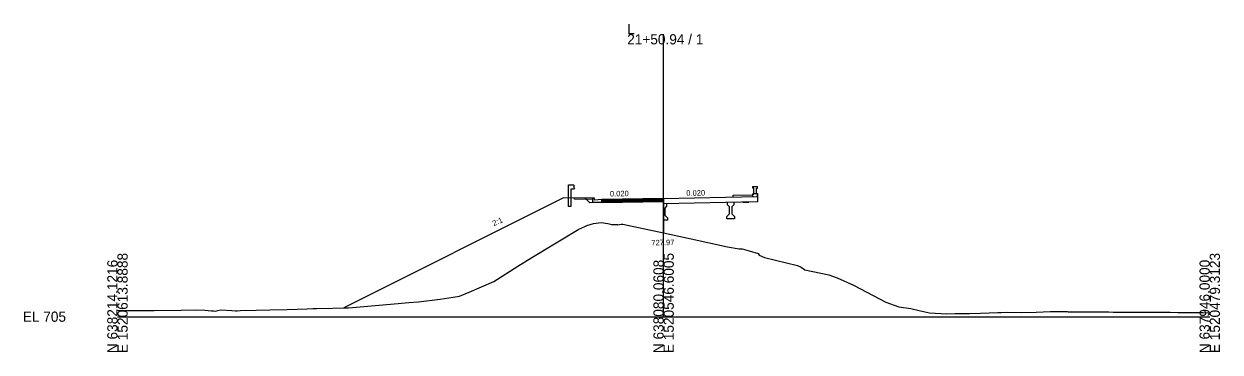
# Model space of a CAD drawing. Extents: x -26 to 3903, y -10 to 9531.
# Drawn here: x 2274.3 to 2602.8, y 490.3 to 580.3 of the extents above; entities that cross this region are included whole.
import ezdxf

# ---------------------------------------------------------------- set-up
doc = ezdxf.new("R2010")
doc.units = 0
for name, color, linetype in [('Exist Cross Section Cell', 7, 'Continuous'), ('Exist XS Center Line Elevation Label', 7, 'Continuous'), ('Exist XS Ground Line', 7, 'Continuous'), ('Old_Level_63', 7, 'Continuous'), ('Prop CMT Guardrail Graphics', 7, 'Continuous'), ('Prop CMT Pvmt Course 1', 7, 'Continuous'), ('Prop CMT Pvmt Course 2', 7, 'Continuous'), ('Prop CMT Pvmt Course 3', 7, 'Continuous'), ('Prop CMT Pvmt Surface', 7, 'Continuous'), ('Prop CMT Slope Grass', 7, 'Continuous'), ('Prop CMT Subgrade Earthwork', 7, 'Continuous'), ('Prop XS Conc Monolithic Island', 7, 'Continuous'), ('Prop XS Earthwork Shape', 7, 'Continuous'), ('Prop XS Finish Grade', 7, 'Continuous'), ('Prop XS Finish Grade Concrete', 7, 'Continuous'), ('Prop XS SE Text', 7, 'Continuous'), ('Prop XS Side Slope Text', 7, 'Continuous')]:
    doc.layers.add(name, color=color, linetype=linetype)

msp = doc.modelspace()

# ---------------------------------------------------------------- linework, layer by layer
at = {"layer": 'Exist Cross Section Cell'}
for p, q in [((2450, 500), (2450, 577.45)), ((2300, 500), (2450, 500)), ((2450, 500), (2600, 500))]:
    msp.add_line(p, q, dxfattribs=at)
at = {"layer": 'Exist XS Ground Line'}
msp.add_lwpolyline([(2300, 501.78), (2301.58, 501.71), (2310.09, 501.71), (2317.52, 501.78), (2321.61, 501.89), (2323.99, 501.76), (2325.83, 501.62), (2326.47, 501.58), (2326.93, 501.51), (2327.56, 501.69), (2328.41, 501.87), (2331.44, 501.74), (2332.45, 501.62), (2332.84, 501.63), (2333.69, 501.65), (2338.1, 501.81), (2341.83, 501.86), (2346.57, 501.94), (2352.12, 502.16), (2353.7, 502.24), (2354.74, 502.28), (2363.47, 502.47), (2364.51, 502.52), (2378.06, 503.7), (2379, 503.76), (2380.03, 503.85), (2382.69, 504.11), (2388.59, 504.76), (2392.16, 505.37), (2393.94, 505.58), (2396.56, 506.74), (2403.34, 509.61), (2409.94, 513.84), (2413.83, 516.23), (2426.69, 524.03), (2428.32, 524.75), (2428.95, 524.99), (2430.74, 525.56), (2432.85, 525.82), (2434.66, 525.54), (2435.09, 525.43), (2435.67, 525.26), (2436.69, 525.26), (2437.35, 525.29), (2437.42, 525.17), (2438.32, 525.32), (2438.84, 525.34), (2450, 522.97), (2452.06, 522.53), (2457.59, 521.33), (2467.51, 519.16), (2470.73, 518.59), (2471.58, 518.57), (2473.46, 518.09), (2475.95, 517.3), (2476.26, 516.89), (2477.72, 516.26), (2486.79, 514.03), (2487.74, 513.61), (2488.83, 512.82), (2495.37, 511.48), (2497.64, 510.68), (2502.19, 508.65), (2511.06, 503.97), (2514.6, 502.67), (2517.91, 502.26), (2520.56, 501.58), (2523.05, 501.09), (2527.79, 500.78), (2530.11, 500.84), (2534.06, 500.9), (2537.01, 500.97), (2541.79, 501.15), (2542.69, 501.18), (2544.15, 501.2), (2548.35, 501.18), (2552.3, 501.27), (2556.2, 501.38), (2558.87, 501.42), (2560.31, 501.38), (2560.81, 501.38), (2561.12, 501.37), (2562.54, 501.36), (2564.02, 501.36), (2564.69, 501.35), (2565.65, 501.35), (2566.19, 501.35), (2566.68, 501.34), (2568.21, 501.33), (2569.53, 501.31), (2569.86, 501.31), (2570.28, 501.3), (2572.33, 501.29), (2573.51, 501.28), (2575.13, 501.27), (2575.86, 501.27), (2577.92, 501.26), (2579.1, 501.25), (2580.73, 501.24), (2581.44, 501.24), (2583.51, 501.23), (2585.64, 501.22), (2586.53, 501.22), (2586.98, 501.22), (2588.41, 501.21), (2589.12, 501.2), (2591.27, 501.19), (2592.12, 501.18), (2592.54, 501.18), (2594.48, 501.19), (2594.84, 501.19), (2596.24, 501.16), (2597.6, 501.13), (2598.12, 501.12), (2599.57, 501.09), (2600, 501.09)], dxfattribs=at)
at = {"layer": 'Old_Level_63'}
for p, q in [((2431, 531.95), (2431, 532.45)), ((2433, 532.1), (2431, 531.95))]:
    msp.add_line(p, q, dxfattribs=at)
for points in [[(2425.5, 532.21), (2425.5, 532.55)], [(2430.5, 532.46), (2430.5, 532.12)], [(2430.5, 532.45), (2430.5, 531.42), (2433, 531.51)], [(2430.5, 532.11), (2425.5, 532.21)], [(2433, 531.51), (2433, 532.1)]]:
    msp.add_lwpolyline(points, dxfattribs=at)
at = {"layer": 'Prop CMT Guardrail Graphics'}
for points in [[(2423.9, 530.17), (2423.9, 536.17)], [(2423.9, 536.17), (2425.23, 536.17), (2425.5, 535.88)], [(2425.5, 535.88), (2425.23, 535.58)], [(2425.23, 535.58), (2425.5, 535.29)], [(2425.5, 535.29), (2425.23, 535), (2424.56, 535)], [(2424.56, 535), (2424.56, 530.17)], [(2424.56, 530.17), (2423.9, 530.17)]]:
    msp.add_lwpolyline(points, dxfattribs=at)
at = {"layer": 'Prop CMT Pvmt Course 1'}
msp.add_line((2450, 532.44), (2433, 532.1), dxfattribs=at)
msp.add_lwpolyline([(2433, 531.85), (2450, 532.19)], dxfattribs=at)
at = {"layer": 'Prop CMT Pvmt Course 2'}
for points in [[(2450, 532.19), (2433, 531.85)], [(2433, 531.85), (2433, 531.51)], [(2433, 531.51), (2450, 531.85)]]:
    msp.add_lwpolyline(points, dxfattribs=at)
at = {"layer": 'Prop CMT Pvmt Course 3'}
for points in [[(2450, 531.85), (2433, 531.51)], [(2433, 531.26), (2450, 531.6)]]:
    msp.add_lwpolyline(points, dxfattribs=at)
at = {"layer": 'Prop CMT Pvmt Surface'}
msp.add_line((2450, 532.44), (2433, 532.1), dxfattribs=at)
msp.add_lwpolyline([(2450, 532.44), (2433, 532.1)], dxfattribs=at)
at = {"layer": 'Prop CMT Slope Grass'}
for p, q in [((2430.5, 532.45), (2422.5, 532.61)), ((2450, 532.44), (2450, 522.98))]:
    msp.add_line(p, q, dxfattribs=at)
msp.add_lwpolyline([(2422.5, 532.61), (2362.17, 502.44)], dxfattribs=at)
at = {"layer": 'Prop CMT Subgrade Earthwork'}
for points in [[(2433, 531.26), (2429.74, 531.2), (2428.46, 532.49)], [(2450, 531.6), (2433, 531.26)]]:
    msp.add_lwpolyline(points, dxfattribs=at)
at = {"layer": 'Prop XS Conc Monolithic Island'}
for p, q in [((2474.53, 535.21), (2474.53, 535.71)), ((2474.53, 535.71), (2475.78, 535.71)), ((2475.78, 535.21), (2475.78, 535.71)), ((2474.78, 535.21), (2474.53, 535.21)), ((2474.53, 532.95), (2474.53, 533.71)), ((2474.53, 533.71), (2474.78, 533.71)), ((2474.78, 533.71), (2474.78, 535.21)), ((2475.53, 533.71), (2475.53, 535.21)), ((2475.53, 535.21), (2475.78, 535.21)), ((2475.78, 533.71), (2475.53, 533.71)), ((2475.78, 532.95), (2475.78, 533.71))]:
    msp.add_line(p, q, dxfattribs=at)
for points in [[(2450, 532.44), (2467, 532.78), (2475.78, 532.95)], [(2475.75, 532.98), (2475.78, 531.45)], [(2475.78, 531.45), (2467, 531.28), (2450, 530.94)], [(2450.83, 530.27), (2450.33, 529.77)], [(2450.33, 529.77), (2450.33, 527.85)], [(2450.83, 530.95), (2450.83, 530.27)], [(2467.59, 530.64), (2467.59, 531.29)], [(2468.09, 530.14), (2467.59, 530.64)], [(2468.09, 528.22), (2468.09, 530.14)], [(2469.26, 530.64), (2468.76, 530.14)], [(2468.76, 530.14), (2468.76, 528.22)], [(2469.26, 531.32), (2469.26, 530.64)], [(2471.75, 531.37), (2472.58, 531.39), (2473.42, 531.4)], [(2451.08, 526.44), (2450, 526.44)], [(2450.33, 527.85), (2451.08, 527.1)], [(2451.08, 527.1), (2451.08, 526.44)], [(2467.34, 527.47), (2468.09, 528.22)], [(2467.34, 526.8), (2467.34, 527.47)], [(2469.51, 526.8), (2468.42, 526.8), (2467.34, 526.8)], [(2468.76, 528.22), (2469.51, 527.47)], [(2469.51, 527.47), (2469.51, 526.8)]]:
    msp.add_lwpolyline(points, dxfattribs=at)
at = {"layer": 'Prop XS Earthwork Shape'}
for points in [[(2363.47, 502.47), (2364.51, 502.52), (2378.06, 503.7), (2379, 503.76), (2380.03, 503.85), (2382.69, 504.11), (2388.59, 504.76), (2392.16, 505.37), (2393.94, 505.58), (2396.56, 506.74), (2403.34, 509.61), (2409.94, 513.84), (2413.83, 516.23), (2426.69, 524.03), (2428.32, 524.75), (2428.95, 524.99), (2430.74, 525.56), (2432.85, 525.82), (2434.66, 525.54), (2435.09, 525.43), (2435.67, 525.26), (2436.69, 525.26), (2437.35, 525.29), (2437.42, 525.17), (2438.32, 525.32), (2438.84, 525.34), (2450, 522.98), (2450, 531.6), (2433, 531.26), (2429.74, 531.2), (2428.46, 532.49), (2422.5, 532.61), (2362.17, 502.44)], [(2434.66, 525.54), (2435.09, 525.43), (2435.67, 525.26), (2436.69, 525.26), (2437.35, 525.29), (2437.42, 525.17), (2438.32, 525.32), (2438.84, 525.34), (2450, 522.98), (2450, 531.6), (2433, 531.26), (2429.74, 531.2), (2428.46, 532.49), (2422.5, 532.61), (2362.17, 502.44), (2363.47, 502.47), (2364.51, 502.52), (2378.06, 503.7), (2379, 503.76), (2380.03, 503.85), (2382.69, 504.11), (2388.59, 504.76), (2392.16, 505.37), (2393.94, 505.58), (2396.56, 506.74), (2403.34, 509.61), (2409.94, 513.84), (2413.83, 516.23), (2426.69, 524.03), (2428.32, 524.75), (2428.95, 524.99), (2430.74, 525.56), (2432.85, 525.82)]]:
    msp.add_lwpolyline(points, close=True, dxfattribs=at)
at = {"layer": 'Prop XS Finish Grade'}
msp.add_line((2469.07, 532.82), (2469.07, 533.32), dxfattribs=at)
msp.add_lwpolyline([(2469.07, 532.82), (2469.07, 533.32), (2474.57, 533.43), (2474.57, 533.77), (2475.78, 533.77), (2475.78, 532.95)], dxfattribs=at)
at = {"layer": 'Prop XS Finish Grade Concrete'}
msp.add_lwpolyline([(2433, 532.1), (2431, 531.95), (2431, 532.45), (2430.5, 532.45)], dxfattribs=at)

# ---------------------------------------------------------------- texts
at = {"layer": 'Exist Cross Section Cell'}
for s, p in [('L', (2440, 577.45)), ('21+50.94 / 1', (2440, 574.65)), ('EL 705', (2274, 498.6))]:
    msp.add_text(s, height=2.8, dxfattribs=at).set_placement(p)
for s, p in [('E 1520613.8888', (2302.8, 490)), ('E 1520546.6005', (2452.8, 490)), ('E 1520479.3123', (2602.8, 490)), ('N 638214.1216', (2300, 490)), ('N 638080.0608', (2450, 490)), ('N 637946.0000', (2600, 490))]:
    msp.add_text(s, height=2.8, rotation=90, dxfattribs=at).set_placement(p)
at = {"layer": 'Exist XS Center Line Elevation Label'}
msp.add_text('727.97', height=1.5, rotation=0.8401, dxfattribs=at).set_placement((2446.65, 519.54))
at = {"layer": 'Prop XS SE Text'}
for p in [(2435.26, 532.95), (2456.24, 533.13)]:
    msp.add_text('0.020', height=1.5, rotation=1.1458, dxfattribs=at).set_placement(p)
at = {"layer": 'Prop XS Side Slope Text'}
msp.add_text('2:1', height=1.5, rotation=23.9099, dxfattribs=at).set_placement((2403.37, 524.8))

doc.saveas('drawing.dxf')
